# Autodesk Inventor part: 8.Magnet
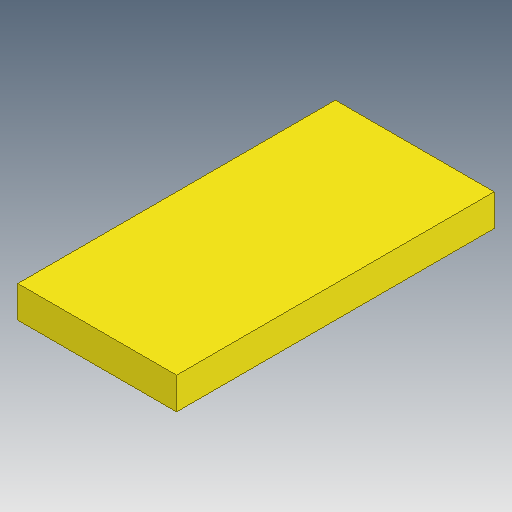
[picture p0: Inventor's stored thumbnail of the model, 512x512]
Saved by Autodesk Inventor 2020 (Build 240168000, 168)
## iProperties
Created: 2022-02
Part Number: 8.Magnet
Material: Steel
Document SubType Name: Modeling
Designer: marti
Density: 7.85 g/cm^3
Appearance: Plate
Mass: 3.14 g
Surface Area: 5.2 cm^2
Volume: 0.4 cm^3
Author: marti
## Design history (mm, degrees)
sketch "Sketch1"
  geometry: L1 (5, 10)-(-5, 10); L2 (-5, 10)-(-5, -10); L3 (-5, -10)-(5, -10); L4 (5, -10)-(5, 10); L5 (5, 10)-(-5, -10); L6 (-5, 10)-(5, -10); 1 further point
  constraints: 12 end point, 2 midpoint, 2 parallel, 1 horizontal, 1 perpendicular
  dimensions: "d0" = 10 distance of L3.end L2.end; "d1" = 20 distance of L2.end L1.end
extrude "Extrusion1" new body sketch "Sketch1" distance "d2" = 2; taper "d3" = 0 deg
body "Solid1"
